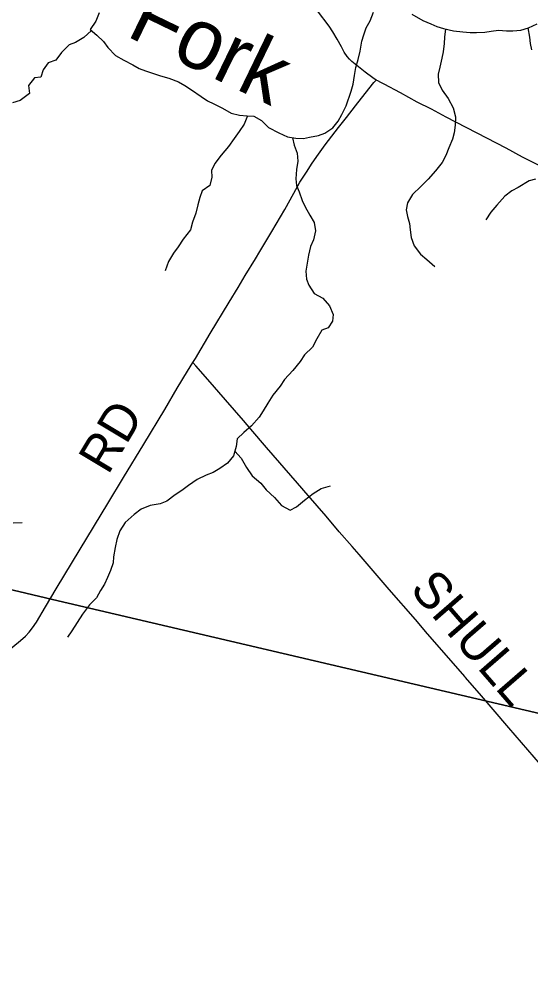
# Model space of a CAD drawing. Extents: x 1442749 to 1756758, y 235267 to 677782.
# Drawn here: x 1561966 to 1566168, y 488495 to 496421 of the extents above; entities that cross this region are included whole.
import ezdxf

# ---------------------------------------------------------------- set-up
doc = ezdxf.new("R2010")
doc.units = 0
for name, color, linetype in [('GM_X_Minor_River', 7, 'Continuous'), ('GM_X_Minor_River_Text', 7, 'Continuous'), ('GM_X_Township', 7, 'Continuous'), ('GM_X_Township_Road', 7, 'Continuous'), ('GM_X_Township_Road_Text', 7, 'Continuous')]:
    doc.layers.add(name, color=color, linetype=linetype)

msp = doc.modelspace()

# ---------------------------------------------------------------- linework, layer by layer
at = {"layer": 'GM_X_Minor_River'}
for points in [[(1562622.6, 496473.5), (1562593.6, 496405.8), (1562548.5, 496338.2), (1562601.9, 496289.4), (1562659.2, 496238.5), (1562694.5, 496187.9), (1562755.6, 496122.9), (1562825.1, 496083.9), (1562898.6, 496046.8), (1562950.3, 496016.1), (1563002, 495997.3), (1563069.8, 495976.4), (1563125.6, 495955.6), (1563195.3, 495936.6), (1563273, 495905.5), (1563326.6, 495876.7), (1563382.1, 495839.8), (1563461.4, 495786.6), (1563513, 495749.9), (1563564.6, 495725.1), (1563636.2, 495690.1), (1563707.7, 495649), (1563775.5, 495632.1), (1563837.5, 495627.2), (1563893.5, 495624.5), (1563957.1, 495589.5), (1564014.3, 495530.6), (1564097.7, 495487.4), (1564169.3, 495454.3), (1564237.2, 495443.4), (1564301.3, 495442.5), (1564351.5, 495451.9), (1564423.8, 495466.9), (1564476.1, 495486.3), (1564542.8, 495529.5), (1564585.6, 495585), (1564616.4, 495638.7), (1564651.5, 495710.4)], [(1564651.5, 495710.4), (1564693.3, 495830.1), (1564710.2, 495888), (1564721.2, 495960), (1564732.2, 496026), (1564749.1, 496089.9), (1564766.2, 496159.8), (1564781.3, 496239.8), (1564798.1, 496293.7), (1564817, 496351.6), (1564849.8, 496407.3), (1564876.9, 496479.1)], [(1565191, 496462.8), (1565282.3, 496411.4), (1565346, 496382.5), (1565397.7, 496361.8), (1565451.5, 496345), (1565533.3, 496325.8), (1565611.3, 496318.8), (1565669.3, 496312), (1565721.3, 496311.2), (1565789.5, 496316.3), (1565841.6, 496323.6), (1565903.8, 496330.8), (1565969.8, 496325.9), (1566019.8, 496325.2), (1566086, 496330.3), (1566148.3, 496351.5), (1566220.9, 496384.6)], [(1562559.8, 496327.9), (1562497.5, 496270.7), (1562426.8, 496229.6), (1562376.5, 496210.2), (1562311.5, 496147), (1562266.6, 496085.5), (1562202.2, 496064.3), (1562161.3, 496006.7), (1562142.4, 495944.8), (1562090.3, 495939.5), (1562041.3, 495878), (1562050.4, 495809.8), (1561973.5, 495752.7), (1561909.1, 495733.5)], [(1565467.8, 496341.2), (1565460.5, 496272.7), (1565457.8, 496222.6), (1565448.7, 496152.6), (1565438, 496100.6), (1565420.9, 496026.7), (1565408.1, 495970.7), (1565409.1, 495902.6), (1565440.2, 495838), (1565489.2, 495771.2), (1565530.2, 495694.5), (1565551.1, 495620), (1565548.1, 495551.9), (1565539.2, 495487.9), (1565524.4, 495436), (1565495.3, 495364.2), (1565470.4, 495302.4), (1565439.5, 495244.7), (1565384.5, 495175.3), (1565325.4, 495105.9), (1565264.5, 495046.6), (1565195.5, 494981.4), (1565154.5, 494913.8), (1565145.6, 494855.8), (1565156.8, 494801.5), (1565172, 494743.2), (1565177.2, 494691), (1565184.3, 494628.8), (1565211.3, 494558.2), (1565262.4, 494489.4), (1565313.8, 494446.6), (1565381.1, 494389.6)], [(1566145.3, 496350.5), (1566157.2, 496273.3), (1566164.4, 496221), (1566173.7, 496170.8)], [(1563839.8, 495627.1), (1563814.5, 495559.4), (1563773.6, 495499.8), (1563730.7, 495442.2), (1563685.7, 495374.7), (1563624.6, 495303.4), (1563573.5, 495235.9), (1563544.7, 495178.2), (1563547.9, 495124), (1563530.9, 495056.1), (1563468.2, 495010.8), (1563449.3, 494955), (1563432.5, 494897.1), (1563415.5, 494827.1), (1563390.4, 494753.3), (1563373.4, 494691.4), (1563312.3, 494614), (1563271.3, 494550.5), (1563232.5, 494498.9), (1563191.5, 494429.3), (1563164.3, 494353.5)], [(1564210.4, 495447.7), (1564224.4, 495385.5), (1564249.5, 495321), (1564254.5, 495254.8), (1564243.5, 495186.7), (1564238.4, 495108.6), (1564243.6, 495054.4), (1564264.8, 495002), (1564289.8, 494931.5), (1564315.1, 494879.1), (1564354.2, 494812.4), (1564389.3, 494751.8), (1564400.3, 494681.5), (1564383.2, 494607.5), (1564358.4, 494553.8), (1564343.4, 494483.8), (1564330.4, 494415.8), (1564319.5, 494351.8), (1564324.5, 494285.6), (1564343.8, 494235.2), (1564388.9, 494168.5), (1564460.4, 494129.4), (1564513.5, 494066.6), (1564544.5, 493994), (1564539.7, 493940), (1564502.9, 493886.3), (1564452.6, 493867), (1564411.5, 493795.3), (1564374.4, 493725.7), (1564309.5, 493662.4), (1564274.6, 493608.8), (1564213.5, 493533.4), (1564144.4, 493460.2), (1564109.5, 493406.6), (1564048.4, 493333.2), (1564007.4, 493265.6), (1563968.4, 493202), (1563935.6, 493150.3), (1563874.6, 493081), (1563811.7, 493025.7), (1563756.9, 492974.4), (1563748, 492910.3), (1563724.8, 492832.5), (1563677.9, 492773), (1563613.2, 492729.8), (1563558.7, 492696.4), (1563502.3, 492675.1), (1563427.7, 492638.1), (1563356.9, 492588.9), (1563300.3, 492547.6), (1563247.7, 492512.2), (1563176.9, 492461.1), (1563122.5, 492437.8), (1563040.2, 492424.8), (1562967.7, 492395.7), (1562909, 492350.4), (1562836, 492285.3), (1562790.9, 492215.7), (1562767.9, 492145.9), (1562752.9, 492079.9), (1562739.8, 492004), (1562737.1, 491953.9), (1562714.1, 491890), (1562691.3, 491832.2), (1562666.5, 491778.4), (1562633.7, 491726.8), (1562600.8, 491667.1), (1562543.9, 491609.7), (1562486.7, 491532.3), (1562441.7, 491464.8), (1562398.7, 491395.2), (1562361.9, 491343.6)], [(1566208.3, 495106), (1566156.1, 495094.6), (1566065.2, 495039.7), (1566012.7, 495010.4), (1565956, 494967.1), (1565888.9, 494893.8), (1565840, 494836.3), (1565799.1, 494772.8)], [(1563736.2, 492870.8), (1563788.6, 492813.6), (1563833.6, 492738.8), (1563880.6, 492670), (1563949.8, 492608.9), (1563993.1, 492554.2), (1564062.2, 492491.1), (1564121.3, 492426.2), (1564192.8, 492387.2), (1564243.3, 492414.5), (1564308.2, 492469.8), (1564381, 492522.9), (1564445.6, 492564.1), (1564522.1, 492587.1)], [(1561915, 492283.7), (1561989.1, 492284.7)]]:
    msp.add_lwpolyline(points, dxfattribs=at)
at = {"layer": 'GM_X_Township'}
for points in [[(1574678.9, 502300.3), (1573761.6, 498985.6), (1572955, 496034.6), (1572409.7, 494039.3), (1571163.6, 489560), (1570397.4, 489739.7), (1565724.7, 490835.9), (1562239.9, 491653.5), (1557897.1, 492683), (1551075.3, 494300.3), (1546804.5, 495312.8), (1545137.5, 495708), (1545013, 495737.5), (1545078, 496425), (1545352.6, 499330.6), (1545798, 504043.7)], [(1543135.8, 476031.3), (1543818, 482923.1), (1543861.4, 483361.9), (1544122.7, 486001.5), (1544211.7, 487255.6), (1544428.8, 489554.2), (1545002.2, 495623.2), (1545013, 495737.5), (1545137.5, 495708), (1546804.5, 495312.8), (1551075.3, 494300.3), (1557897.1, 492683), (1562239.9, 491653.5), (1565724.7, 490835.9), (1570397.4, 489739.7)]]:
    msp.add_lwpolyline(points, dxfattribs=at)
at = {"layer": 'GM_X_Township_Road'}
for points in [[(1564897.4, 495921.6), (1564871.2, 495939.5), (1564808.7, 495986.9), (1564780.1, 496008.9), (1564698.1, 496074.6), (1564679.1, 496093.2), (1564660.2, 496116.2), (1564636.2, 496151.8), (1564612.4, 496194.9), (1564578.2, 496258.2), (1564543, 496317.1), (1564511.8, 496363), (1564415.2, 496491.2)], [(1563392.6, 493599.6), (1563413.5, 493634), (1563533.5, 493838.8), (1563690, 494096.9), (1563763.2, 494217.4), (1563822.7, 494315.7), (1563906.3, 494452.9), (1563941.5, 494512.1), (1564041.9, 494677.3), (1564148.6, 494857.3), (1564222.5, 494992.2), (1564272.2, 495081), (1564324.4, 495164.6), (1564373.3, 495238.6), (1564423.9, 495311.5), (1564480.1, 495388.4), (1564589.5, 495531.8), (1564653.8, 495614.7), (1564727.6, 495711), (1564807.9, 495810.7), (1564879.4, 495900.3), (1564897.4, 495921.6)], [(1566982.1, 494706.5), (1566950.5, 494734.1), (1566909.7, 494771.3), (1566868.4, 494815), (1566821.7, 494871.2), (1566780.5, 494918.5), (1566754.6, 494943), (1566729.2, 494963.2), (1566699.2, 494982.5), (1566643.9, 495010.9), (1566460.1, 495102.2), (1566232.3, 495222.1), (1566101.5, 495288.9), (1565966.7, 495360.4), (1565726.9, 495484.4), (1565551.3, 495576.4), (1565473, 495617.8), (1565352.3, 495681.2), (1565235.9, 495740.8), (1565098.9, 495815.3), (1564963.5, 495886.6), (1564937.7, 495900.1), (1564911.5, 495914), (1564897.4, 495921.6)], [(1562268.4, 491739.6), (1562465.7, 492065.5), (1562694.3, 492441), (1562823.4, 492654.3), (1562989.2, 492929.8), (1563160.6, 493213.3), (1563264.4, 493388.2), (1563349, 493528.2), (1563392.6, 493599.6)], [(1565628.3, 491014.7), (1565625.7, 491019), (1565380.5, 491301.2), (1565320.8, 491371), (1565219.9, 491487.6), (1565004.8, 491735.3), (1564759.2, 492021.7), (1564700.8, 492088.4), (1564595.3, 492209.5), (1564486.5, 492336.6), (1564339, 492508.3), (1564253, 492607.5), (1563997.4, 492902.5), (1563869, 493051.5), (1563807.1, 493123.8), (1563661.1, 493292.4), (1563515, 493460.9), (1563417.2, 493571.7), (1563392.6, 493599.6)], [(1559992.1, 489722.7), (1560004.6, 489729.3), (1560021.7, 489738.2), (1560040.5, 489751.3), (1560130.9, 489827.9), (1560267.9, 489940.4), (1560489.8, 490119.9), (1560747.7, 490328), (1561133.6, 490638.6), (1561642.1, 491048.1), (1561832.4, 491198.8), (1561977.3, 491316.7), (1562016.2, 491351.5), (1562047.4, 491384.5), (1562075.6, 491420.2), (1562106.2, 491466.4), (1562181.9, 491593), (1562268.4, 491739.6)], [(1568523.2, 487650.9), (1568511.6, 487664.7), (1568396, 487802.2), (1568084.4, 488161.7), (1567906.6, 488367.9), (1567724.2, 488578.8), (1567616.9, 488702.9), (1567405.5, 488949.5), (1567379.5, 488979), (1567243.1, 489138.6), (1566900.7, 489536.5), (1566567.2, 489924.6), (1566248.9, 490295.7), (1565987, 490598.4), (1565745.9, 490880), (1565628.3, 491014.7)]]:
    msp.add_lwpolyline(points, dxfattribs=at)

# ---------------------------------------------------------------- texts
at = {"layer": 'GM_X_Minor_River_Text'}
msp.add_text('Fork', height=499.96, rotation=334.17159, dxfattribs=at).set_placement((1562831.7, 496289.3))
at = {"layer": 'GM_X_Township_Road_Text'}
for s, rotation, p in [('RD', 59.0442, (1562695.2, 492669.9)), ('SHULL', 310.96685, (1565166.9, 491731.4))]:
    msp.add_text(s, height=300, rotation=rotation, dxfattribs=at).set_placement(p)

doc.saveas('drawing.dxf')
